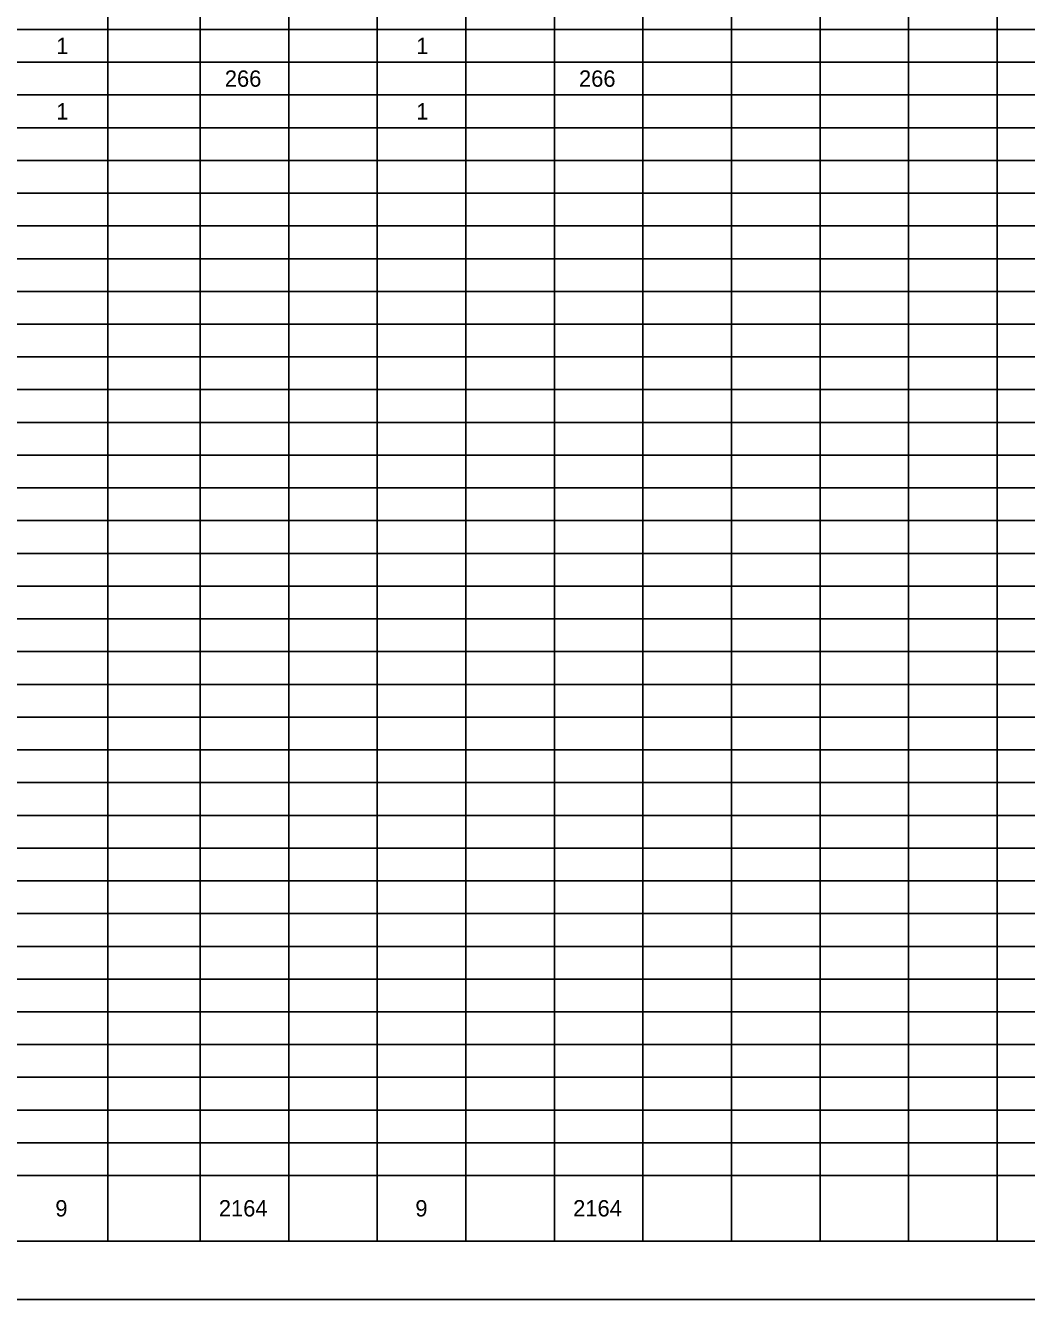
# Model space of a CAD drawing. Extents: x 0 to 34, y 0 to 22.
# Drawn here: x 16.87 to 25.44, y 0 to 10.89 of the extents above; entities that cross this region are included whole.
import ezdxf

# ---------------------------------------------------------------- set-up
doc = ezdxf.new("R2010")
doc.units = 0
for name, color, linetype in [('SH_Border', 7, 'Continuous'), ('SH_Cut_Line', 7, 'Continuous'), ('SH_Text', 7, 'Continuous')]:
    doc.layers.add(name, color=color, linetype=linetype)

msp = doc.modelspace()

# ---------------------------------------------------------------- linework, layer by layer
at = {"layer": 'SH_Border'}
msp.add_lwpolyline([(1.5, 21.5), (33.5, 21.5), (33.5, 0.5), (1.5, 0.5)], close=True, dxfattribs=at)
at = {"layer": 'SH_Cut_Line'}
msp.add_lwpolyline([(0, 0), (34, 0), (34, 22), (0, 22)], close=True, dxfattribs=at)
at = {"layer": 'SH_Text'}
for p, q in [((17.575, 21.5), (17.575, 0.5)), ((18.366, 21.5), (18.366, 0.5)), ((19.124, 21.5), (19.124, 0.5)), ((19.881, 21.5), (19.881, 0.5)), ((20.639, 21.5), (20.639, 0.5)), ((21.396, 21.5), (21.396, 0.5)), ((22.154, 21.5), (22.154, 0.5)), ((22.912, 21.5), (22.912, 0.5)), ((23.669, 21.5), (23.669, 0.5)), ((24.427, 21.5), (24.427, 0.5)), ((25.185, 21.5), (25.185, 0.5)), ((1.5, 10.86), (31.987, 10.86)), ((1.5, 10.58), (31.987, 10.58)), ((1.5, 10.3), (31.987, 10.3)), ((1.5, 10.02), (31.987, 10.02)), ((1.5, 9.74), (31.987, 9.74)), ((1.5, 9.46), (31.987, 9.46)), ((1.5, 9.18), (31.987, 9.18)), ((1.5, 8.9), (31.987, 8.9)), ((1.5, 8.62), (31.987, 8.62)), ((1.5, 8.34), (31.987, 8.34)), ((1.5, 8.06), (31.987, 8.06)), ((1.5, 7.78), (31.987, 7.78)), ((1.5, 7.5), (31.987, 7.5)), ((1.5, 7.22), (31.987, 7.22)), ((1.5, 6.94), (31.987, 6.94)), ((1.5, 6.66), (31.987, 6.66)), ((1.5, 6.38), (31.987, 6.38)), ((1.5, 6.1), (31.987, 6.1)), ((1.5, 5.82), (31.987, 5.82)), ((1.5, 5.54), (31.987, 5.54)), ((1.5, 5.26), (31.987, 5.26)), ((1.5, 4.98), (31.987, 4.98)), ((1.5, 4.7), (31.987, 4.7)), ((1.5, 4.42), (31.987, 4.42)), ((1.5, 4.14), (31.987, 4.14)), ((1.5, 3.86), (31.987, 3.86)), ((1.5, 3.58), (31.987, 3.58)), ((1.5, 3.3), (31.987, 3.3)), ((1.5, 3.02), (31.987, 3.02)), ((1.5, 2.74), (31.987, 2.74)), ((1.5, 2.46), (31.987, 2.46)), ((1.5, 2.18), (31.987, 2.18)), ((1.5, 1.9), (31.987, 1.9)), ((1.5, 1.62), (31.987, 1.62)), ((1.5, 1.34), (31.987, 1.34)), ((1.5, 1.06), (31.987, 1.06)), ((1.5, 0.5), (31.987, 0.5))]:
    msp.add_line(p, q, dxfattribs=at)

# ---------------------------------------------------------------- texts
for s, p in [('1', (17.135, 10.65)), ('1', (20.215, 10.65)), ('266', (18.577, 10.37)), ('266', (21.607, 10.37)), ('1', (17.135, 10.09)), ('1', (20.215, 10.09)), ('9', (17.127, 0.71)), ('2164', (18.526, 0.71)), ('9', (20.207, 0.71)), ('2164', (21.557, 0.71))]:
    msp.add_text(s, height=0.14, dxfattribs=at).set_placement(p)

doc.saveas('drawing.dxf')
